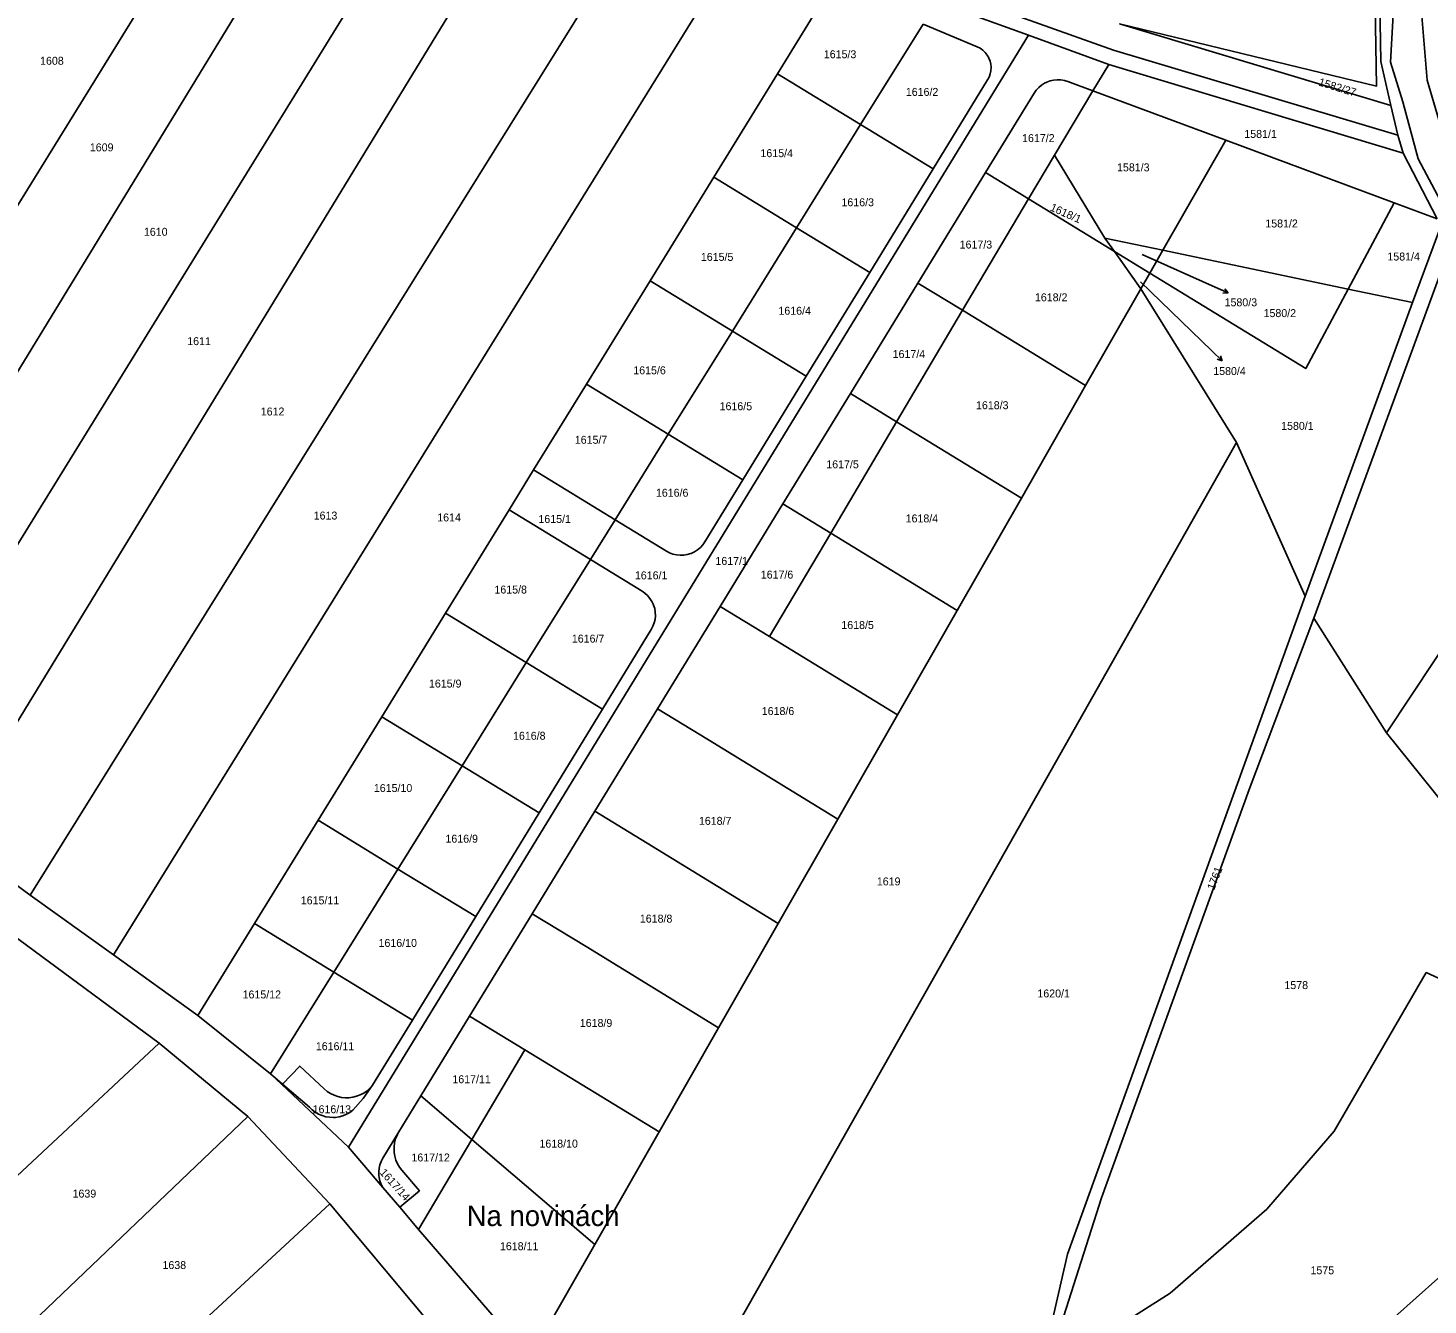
# Model space of a CAD drawing. Extents: x -724107 to -720612, y -1045267 to -1038441.
# Drawn here: x -722795.4 to -722495.8, y -1043452.5 to -1043179.2 of the extents above; entities that cross this region are included whole.
import ezdxf

# ---------------------------------------------------------------- set-up
doc = ezdxf.new("R2010")
doc.units = 0
for name, color, linetype in [('Hranice parcel', 7, 'Continuous'), ('Parcelní čísla', 7, 'Continuous'), ('Pop  PČ popisy', 7, 'Continuous'), ('Vnitřní kresba', 7, 'Continuous')]:
    doc.layers.add(name, color=color, linetype=linetype)

msp = doc.modelspace()

# ---------------------------------------------------------------- linework, layer by layer
at = {"layer": 'Hranice parcel'}
for p, q in [((-722860.89, -1043319.68), (-722731.1, -1043109.44)), ((-722844.89, -1043330.17), (-722715, -1043117.42)), ((-722828.97, -1043340.49), (-722696.75, -1043126.35)), ((-722812.41, -1043351.85), (-722679.88, -1043134.66)), ((-722794.95, -1043364.83), (-722658.09, -1043145.33)), ((-722777.09, -1043377.56), (-722639.25, -1043154.94)), ((-722635, -1043189.04), (-722623.15, -1043169.78)), ((-722600.91, -1043173.73), (-722581.27, -1043180.77)), ((-722617.2, -1043199.93), (-722603.85, -1043178.46)), ((-722603.85, -1043178.46), (-722592.23, -1043183.26)), ((-722503.72, -1043195.83), (-722561.8, -1043178.34)), ((-722726.81, -1043418.74), (-722581.27, -1043180.77)), ((-722581.27, -1043180.77), (-722564.1, -1043187.04)), ((-722564.1, -1043187.04), (-722567.49, -1043192.68)), ((-722564.1, -1043187.04), (-722501.07, -1043206.03)), ((-722648.63, -1043211.18), (-722635, -1043189.04)), ((-722635, -1043189.04), (-722617.2, -1043199.93)), ((-722590.06, -1043190.35), (-722601.7, -1043209.41)), ((-722572.86, -1043190.69), (-722567.49, -1043192.68)), ((-722590.48, -1043210.2), (-722580.07, -1043193.18)), ((-722567.49, -1043192.68), (-722575.75, -1043206.44)), ((-722567.49, -1043192.68), (-722539.05, -1043203.27)), ((-722503.72, -1043195.83), (-722502.27, -1043202.19)), ((-722630.92, -1043222.01), (-722617.2, -1043199.93)), ((-722617.2, -1043199.93), (-722601.7, -1043209.41)), ((-722501.07, -1043206.03), (-722502.27, -1043202.19)), ((-722539.05, -1043203.27), (-722552.5, -1043226.8)), ((-722539.05, -1043203.27), (-722503.05, -1043216.66)), ((-722581.3, -1043215.81), (-722575.75, -1043206.44)), ((-722575.75, -1043206.44), (-722564.93, -1043224.19)), ((-722501.07, -1043206.03), (-722493.82, -1043220.09)), ((-722662.25, -1043233.33), (-722648.63, -1043211.18)), ((-722648.63, -1043211.18), (-722630.92, -1043222.01)), ((-722601.7, -1043209.41), (-722615.26, -1043231.59)), ((-722604.93, -1043233.83), (-722590.48, -1043210.2)), ((-722590.48, -1043210.2), (-722581.3, -1043215.81)), ((-722595.4, -1043239.66), (-722581.3, -1043215.81)), ((-722581.3, -1043215.81), (-722562.91, -1043227.06)), ((-722512.87, -1043235.11), (-722503.05, -1043216.66)), ((-722503.05, -1043216.66), (-722493.82, -1043220.09)), ((-722644.65, -1043244.09), (-722630.92, -1043222.01)), ((-722630.92, -1043222.01), (-722615.26, -1043231.59)), ((-722493.01, -1043221.67), (-722499.08, -1043238)), ((-722552.5, -1043226.8), (-722564.93, -1043224.19)), ((-722564.93, -1043224.19), (-722562.91, -1043227.06)), ((-722490.73, -1043225.28), (-722520.24, -1043305.56)), ((-722562.91, -1043227.06), (-722555.3, -1043231.71)), ((-722562.91, -1043227.06), (-722557.24, -1043235.1)), ((-722552.5, -1043226.8), (-722555.3, -1043231.71)), ((-722512.87, -1043235.11), (-722552.5, -1043226.8)), ((-722615.26, -1043231.59), (-722628.83, -1043253.77)), ((-722555.3, -1043231.71), (-722557.24, -1043235.1)), ((-722675.88, -1043255.47), (-722662.25, -1043233.33)), ((-722662.25, -1043233.33), (-722644.65, -1043244.09)), ((-722619.38, -1043257.46), (-722604.93, -1043233.83)), ((-722604.93, -1043233.83), (-722595.4, -1043239.66)), ((-722557.24, -1043235.1), (-722569.05, -1043255.77)), ((-722536.78, -1043267.98), (-722557.24, -1043235.1)), ((-722499.08, -1043238), (-722512.87, -1043235.11)), ((-722499.08, -1043238), (-722522.06, -1043300.85)), ((-722609.51, -1043263.5), (-722595.4, -1043239.66)), ((-722595.4, -1043239.66), (-722569.05, -1043255.77)), ((-722658.37, -1043266.18), (-722644.65, -1043244.09)), ((-722644.65, -1043244.09), (-722628.83, -1043253.77)), ((-722687.18, -1043273.83), (-722675.88, -1043255.47)), ((-722675.88, -1043255.47), (-722658.37, -1043266.18)), ((-722628.83, -1043253.77), (-722642.39, -1043275.95)), ((-722569.05, -1043255.77), (-722582.81, -1043279.83)), ((-722633.84, -1043281.09), (-722619.38, -1043257.46)), ((-722619.38, -1043257.46), (-722609.51, -1043263.5)), ((-722623.61, -1043287.34), (-722609.51, -1043263.5)), ((-722609.51, -1043263.5), (-722582.81, -1043279.83)), ((-722669.75, -1043284.49), (-722658.37, -1043266.18)), ((-722663.56, -1043492.06), (-722536.78, -1043267.98)), ((-722658.37, -1043266.18), (-722642.39, -1043275.95)), ((-722522.06, -1043300.85), (-722536.78, -1043267.98)), ((-722464.46, -1043269.33), (-722504.64, -1043330.07)), ((-722692.42, -1043282.35), (-722687.18, -1043273.83)), ((-722669.75, -1043284.49), (-722687.18, -1043273.83)), ((-722642.39, -1043275.95), (-722650.52, -1043289.22)), ((-722582.81, -1043279.83), (-722596.56, -1043303.89)), ((-722706.05, -1043304.49), (-722692.42, -1043282.35)), ((-722692.42, -1043282.35), (-722675.03, -1043292.98)), ((-722647.25, -1043303.02), (-722633.84, -1043281.09)), ((-722633.84, -1043281.09), (-722623.61, -1043287.34)), ((-722675.03, -1043292.98), (-722669.75, -1043284.49)), ((-722658.77, -1043291.2), (-722669.75, -1043284.49)), ((-722636.7, -1043309.46), (-722623.61, -1043287.34)), ((-722623.61, -1043287.34), (-722596.56, -1043303.89)), ((-722688.76, -1043315.06), (-722675.03, -1043292.98)), ((-722675.03, -1043292.98), (-722663.99, -1043299.74)), ((-722719.67, -1043326.63), (-722706.05, -1043304.49)), ((-722706.05, -1043304.49), (-722688.76, -1043315.06)), ((-722660.65, -1043324.94), (-722647.25, -1043303.02)), ((-722647.25, -1043303.02), (-722636.7, -1043309.46)), ((-722596.56, -1043303.89), (-722609.31, -1043326.21)), ((-722504.64, -1043330.07), (-722520.24, -1043305.56)), ((-722662, -1043307.98), (-722672.43, -1043325.05)), ((-722636.7, -1043309.46), (-722609.31, -1043326.21)), ((-722702.49, -1043337.15), (-722688.76, -1043315.06)), ((-722688.76, -1043315.06), (-722672.43, -1043325.05)), ((-722672.43, -1043325.05), (-722686, -1043347.23)), ((-722674.06, -1043346.86), (-722660.65, -1043324.94)), ((-722733.3, -1043348.78), (-722719.67, -1043326.63)), ((-722719.67, -1043326.63), (-722702.49, -1043337.15)), ((-722609.31, -1043326.21), (-722622.07, -1043348.54)), ((-722716.21, -1043359.23), (-722702.49, -1043337.15)), ((-722702.49, -1043337.15), (-722686, -1043347.23)), ((-722746.93, -1043370.92), (-722733.3, -1043348.78)), ((-722733.3, -1043348.78), (-722716.21, -1043359.23)), ((-722686, -1043347.23), (-722699.56, -1043369.41)), ((-722687.47, -1043368.79), (-722674.06, -1043346.86)), ((-722622.07, -1043348.54), (-722634.83, -1043370.86)), ((-722812.41, -1043351.85), (-722794.95, -1043364.83)), ((-722729.94, -1043381.31), (-722716.21, -1043359.23)), ((-722716.21, -1043359.23), (-722699.56, -1043369.41)), ((-722794.95, -1043364.83), (-722777.09, -1043377.56)), ((-722767.31, -1043396.47), (-722805.94, -1043368.02)), ((-722699.56, -1043369.41), (-722713.13, -1043391.59)), ((-722700.88, -1043390.71), (-722687.47, -1043368.79)), ((-722759.01, -1043390.56), (-722746.93, -1043370.92)), ((-722746.93, -1043370.92), (-722729.94, -1043381.31)), ((-722634.83, -1043370.86), (-722647.59, -1043393.18)), ((-722777.09, -1043377.56), (-722759.01, -1043390.56)), ((-722743.47, -1043403.08), (-722729.94, -1043381.31)), ((-722729.94, -1043381.31), (-722713.13, -1043391.59)), ((-722743.47, -1043403.08), (-722759.01, -1043390.56)), ((-722711.32, -1043407.78), (-722700.88, -1043390.71)), ((-722689.05, -1043397.95), (-722700.88, -1043390.71)), ((-722713.13, -1043391.59), (-722721.65, -1043405.51)), ((-722647.59, -1043393.18), (-722660.35, -1043415.5)), ((-722767.31, -1043396.47), (-722826.61, -1043451.81)), ((-722748.31, -1043412.22), (-722767.31, -1043396.47)), ((-722700.4, -1043417.12), (-722689.05, -1043397.95)), ((-722689.05, -1043397.95), (-722660.35, -1043415.5)), ((-722740.9, -1043405.29), (-722743.47, -1043403.08)), ((-722726.81, -1043418.74), (-722743.47, -1043403.08)), ((-722735.16, -1043410.22), (-722740.9, -1043405.29)), ((-722716.03, -1043415.48), (-722711.32, -1043407.78)), ((-722711.32, -1043407.78), (-722700.4, -1043417.12)), ((-722748.31, -1043412.22), (-722805.19, -1043466.47)), ((-722730.81, -1043430.91), (-722748.31, -1043412.22)), ((-722719.46, -1043421.1), (-722716.03, -1043415.48)), ((-722711.79, -1043436.38), (-722700.4, -1043417.12)), ((-722700.4, -1043417.12), (-722674.12, -1043439.61)), ((-722660.35, -1043415.5), (-722674.12, -1043439.61)), ((-722461.57, -1043418.14), (-722578.75, -1043522.81)), ((-722719.44, -1043427.4), (-722726.81, -1043418.74)), ((-722715.85, -1043431.62), (-722719.44, -1043427.4)), ((-722730.81, -1043430.91), (-722788.48, -1043484.25)), ((-722700.12, -1043467.52), (-722730.81, -1043430.91)), ((-722711.79, -1043436.38), (-722715.85, -1043431.62)), ((-722688.03, -1043463.94), (-722711.79, -1043436.38)), ((-722674.12, -1043439.61), (-722688.03, -1043463.94))]:
    msp.add_line(p, q, dxfattribs=at)
for points in [[(-722502.27, -1043202.19), (-722563.1, -1043183.97), (-722599.95, -1043170.79), (-722833.48, -1043054.07)], [(-722561.8, -1043178.34), (-722506.78, -1043191.69), (-722507.35, -1043157.3)], [(-722506.38, -1043157.1), (-722505.87, -1043186.38), (-722503.72, -1043195.83)], [(-722592.23, -1043183.26), (-722591.61, -1043183.58), (-722591.05, -1043183.99), (-722590.54, -1043184.47), (-722590.11, -1043185.03), (-722589.77, -1043185.63), (-722589.75, -1043185.67), (-722589.5, -1043186.33), (-722589.35, -1043187.01), (-722589.3, -1043187.7), (-722589.34, -1043188.4), (-722589.49, -1043189.08), (-722589.73, -1043189.74), (-722590.06, -1043190.35)], [(-722580.07, -1043193.18), (-722579.62, -1043192.55), (-722579.1, -1043191.98), (-722578.51, -1043191.48), (-722577.86, -1043191.06), (-722577.39, -1043190.83), (-722576.67, -1043190.56), (-722575.91, -1043190.39), (-722575.14, -1043190.32), (-722574.37, -1043190.34), (-722573.6, -1043190.47), (-722572.86, -1043190.69)], [(-722512.87, -1043235.11), (-722521.93, -1043252.12), (-722555.3, -1043231.71)], [(-722650.52, -1043289.22), (-722650.97, -1043289.85), (-722651.49, -1043290.42), (-722652.08, -1043290.92), (-722652.74, -1043291.34), (-722653.44, -1043291.67), (-722653.55, -1043291.71), (-722654.3, -1043291.93), (-722655.06, -1043292.06), (-722655.83, -1043292.08), (-722656.6, -1043292.01), (-722657.36, -1043291.83), (-722658.08, -1043291.56), (-722658.77, -1043291.2)], [(-722663.99, -1043299.74), (-722663.36, -1043300.19), (-722662.79, -1043300.71), (-722662.29, -1043301.3), (-722661.87, -1043301.96), (-722661.54, -1043302.66), (-722661.5, -1043302.76), (-722661.28, -1043303.5), (-722661.15, -1043304.27), (-722661.12, -1043305.04), (-722661.2, -1043305.81), (-722661.37, -1043306.57), (-722661.64, -1043307.29), (-722662, -1043307.98)], [(-722579.59, -1043469.75), (-722576.99, -1043459.4), (-722572.92, -1043441.68), (-722522.06, -1043300.85)], [(-722520.24, -1043305.56), (-722534.05, -1043342.23), (-722565.66, -1043429.61), (-722577.6, -1043466.92)], [(-722660.65, -1043324.94), (-722649.79, -1043331.58), (-722622.07, -1043348.54)], [(-722504.64, -1043330.07), (-722487.02, -1043351.99), (-722468.23, -1043365.98)], [(-722674.06, -1043346.86), (-722662.88, -1043353.71), (-722634.83, -1043370.86)], [(-722687.47, -1043368.79), (-722675.97, -1043375.83), (-722647.59, -1043393.18)], [(-722483.1, -1043387.35), (-722496.16, -1043381.39), (-722515.89, -1043415.3), (-722530.26, -1043432.02), (-722550.95, -1043450), (-722577.6, -1043466.92)], [(-722740.9, -1043405.29), (-722737.24, -1043401.41), (-722732.01, -1043406.3)], [(-722732.01, -1043406.3), (-722731.36, -1043406.84), (-722730.65, -1043407.29), (-722729.89, -1043407.66), (-722729.1, -1043407.93), (-722728.28, -1043408.11), (-722727.44, -1043408.19), (-722726.72, -1043408.17), (-722725.88, -1043408.07), (-722725.07, -1043407.86), (-722724.28, -1043407.56), (-722723.54, -1043407.17), (-722722.84, -1043406.69), (-722722.21, -1043406.14), (-722721.65, -1043405.51)], [(-722721.65, -1043405.51), (-722723.65, -1043408.37), (-722725.86, -1043410.83)], [(-722725.86, -1043410.83), (-722726.52, -1043411.32), (-722727.24, -1043411.72), (-722728, -1043412.03), (-722728.8, -1043412.25), (-722729.61, -1043412.37), (-722730.01, -1043412.39), (-722730.83, -1043412.36), (-722731.64, -1043412.24), (-722732.44, -1043412.01), (-722733.19, -1043411.69), (-722733.91, -1043411.28), (-722734.57, -1043410.79), (-722735.16, -1043410.22)], [(-722716.03, -1043415.48), (-722716.42, -1043416.22), (-722716.72, -1043417), (-722716.93, -1043417.82), (-722717.04, -1043418.65), (-722717.05, -1043419.05), (-722717.01, -1043419.88), (-722716.87, -1043420.71), (-722716.64, -1043421.52), (-722716.3, -1043422.29), (-722715.88, -1043423.01), (-722715.38, -1043423.68)], [(-722719.44, -1043427.4), (-722719.81, -1043426.71), (-722720.08, -1043425.99), (-722720.26, -1043425.23), (-722720.31, -1043424.82), (-722720.34, -1043424.04), (-722720.26, -1043423.27), (-722720.09, -1043422.52), (-722719.82, -1043421.79), (-722719.46, -1043421.1)], [(-722715.38, -1043423.68), (-722711.64, -1043428.07), (-722715.85, -1043431.62)]]:
    msp.add_lwpolyline(points, dxfattribs=at)
at = {"layer": 'Pop  PČ popisy'}
for p, q in [((-722556.92, -1043227.69), (-722541.31, -1043234.71)), ((-722557.28, -1043233.56), (-722542.01, -1043248.35)), ((-722541.31, -1043234.71), (-722538.57, -1043235.93)), ((-722538.57, -1043235.93), (-722539.28, -1043235.07)), ((-722538.57, -1043235.93), (-722539.69, -1043235.98)), ((-722542.01, -1043248.35), (-722539.85, -1043250.44)), ((-722539.85, -1043250.44), (-722540.92, -1043250.1)), ((-722539.85, -1043250.44), (-722540.22, -1043249.38))]:
    msp.add_line(p, q, dxfattribs=at)
at = {"layer": 'Vnitřní kresba'}
for p, q in [((-722503.78, -1043186.57), (-722499.29, -1043102.35)), ((-722495.97, -1043190.42), (-722497.22, -1043174.99)), ((-722503.78, -1043186.57), (-722501.16, -1043195.01)), ((-722495.97, -1043190.42), (-722491.67, -1043204.93)), ((-722501.16, -1043195.01), (-722497.92, -1043207.22)), ((-722497.92, -1043207.22), (-722488.32, -1043225.27))]:
    msp.add_line(p, q, dxfattribs=at)

# ---------------------------------------------------------------- texts
at = {"layer": 'Parcelní čísla'}
for s, p in [('1615/3', (-722625.08, -1043185.71)), ('1608', (-722792.8, -1043187.11)), ('1616/2', (-722607.53, -1043193.77)), ('1617/2', (-722582.65, -1043203.66)), ('1581/1', (-722535.09, -1043202.76)), ('1609', (-722782.15, -1043205.64)), ('1615/4', (-722638.64, -1043206.88)), ('1581/3', (-722562.33, -1043209.92)), ('1616/3', (-722621.3, -1043217.39)), ('1581/2', (-722530.6, -1043221.93)), ('1610', (-722770.58, -1043223.71)), ('1617/3', (-722596.01, -1043226.44)), ('1615/5', (-722651.39, -1043229.08)), ('1581/4', (-722504.47, -1043229)), ('1618/2', (-722579.9, -1043237.73)), ('1580/3', (-722539.31, -1043238.8)), ('1616/4', (-722634.79, -1043240.6)), ('1580/2', (-722530.97, -1043241.11)), ('1611', (-722761.31, -1043247.11)), ('1617/4', (-722610.35, -1043249.87)), ('1615/6', (-722665.85, -1043253.35)), ('1580/4', (-722541.74, -1043253.51)), ('1616/5', (-722647.38, -1043261.04)), ('1618/3', (-722592.51, -1043260.82)), ('1612', (-722745.57, -1043262.17)), ('1580/1', (-722527.21, -1043265.24)), ('1615/7', (-722678.37, -1043268.22)), ('1617/5', (-722624.55, -1043273.47)), ('1616/6', (-722661.01, -1043279.55)), ('1613', (-722734.25, -1043284.43)), ('1614', (-722707.81, -1043284.84)), ('1615/1', (-722686.16, -1043285.17)), ('1618/4', (-722607.57, -1043285.05)), ('1617/1', (-722648.28, -1043294.15)), ('1616/1', (-722665.51, -1043297.23)), ('1617/6', (-722638.57, -1043297.07)), ('1615/8', (-722695.57, -1043300.27)), ('1618/5', (-722621.33, -1043307.86)), ('1616/7', (-722679, -1043310.77)), ('1615/9', (-722709.58, -1043320.39)), ('1618/6', (-722638.36, -1043326.27)), ('1616/8', (-722691.59, -1043331.56)), ('1615/10', (-722721.37, -1043342.74)), ('1618/7', (-722651.81, -1043349.77)), ('1616/9', (-722706.05, -1043353.59)), ('1619', (-722613.73, -1043362.73)), ('1615/11', (-722737.01, -1043366.79)), ('1618/8', (-722664.45, -1043370.69)), ('1616/10', (-722720.37, -1043375.9)), ('1615/12', (-722749.46, -1043386.92)), ('1620/1', (-722579.37, -1043386.71)), ('1578', (-722526.51, -1043384.92)), ('1618/9', (-722677.3, -1043393.02)), ('1616/11', (-722733.79, -1043398)), ('1617/11', (-722704.57, -1043405.06)), ('1616/13', (-722734.47, -1043411.49)), ('1618/10', (-722685.93, -1043418.85)), ('1617/12', (-722713.33, -1043421.81)), ('1639', (-722785.85, -1043429.54)), ('1618/11', (-722694.39, -1043440.8)), ('1638', (-722766.61, -1043444.83)), ('1575', (-722520.93, -1043445.95))]:
    msp.add_text(s, height=1.7, dxfattribs=at).set_placement(p)
for s, rotation, p in [('1582/27', 343, (-722519.34, -1043191.52)), ('1618/1', 336, (-722576.81, -1043218.24)), ('1761', 69, (-722541.54, -1043363.86)), ('1617/14', 312, (-722720.24, -1043424.27))]:
    msp.add_text(s, height=1.7, rotation=rotation, dxfattribs=at).set_placement(p)
at = {"layer": 'Pop  PČ popisy'}
msp.add_text('Na novinách', height=4.4, dxfattribs=at).set_placement((-722701.51, -1043435.64))

doc.saveas('drawing.dxf')
